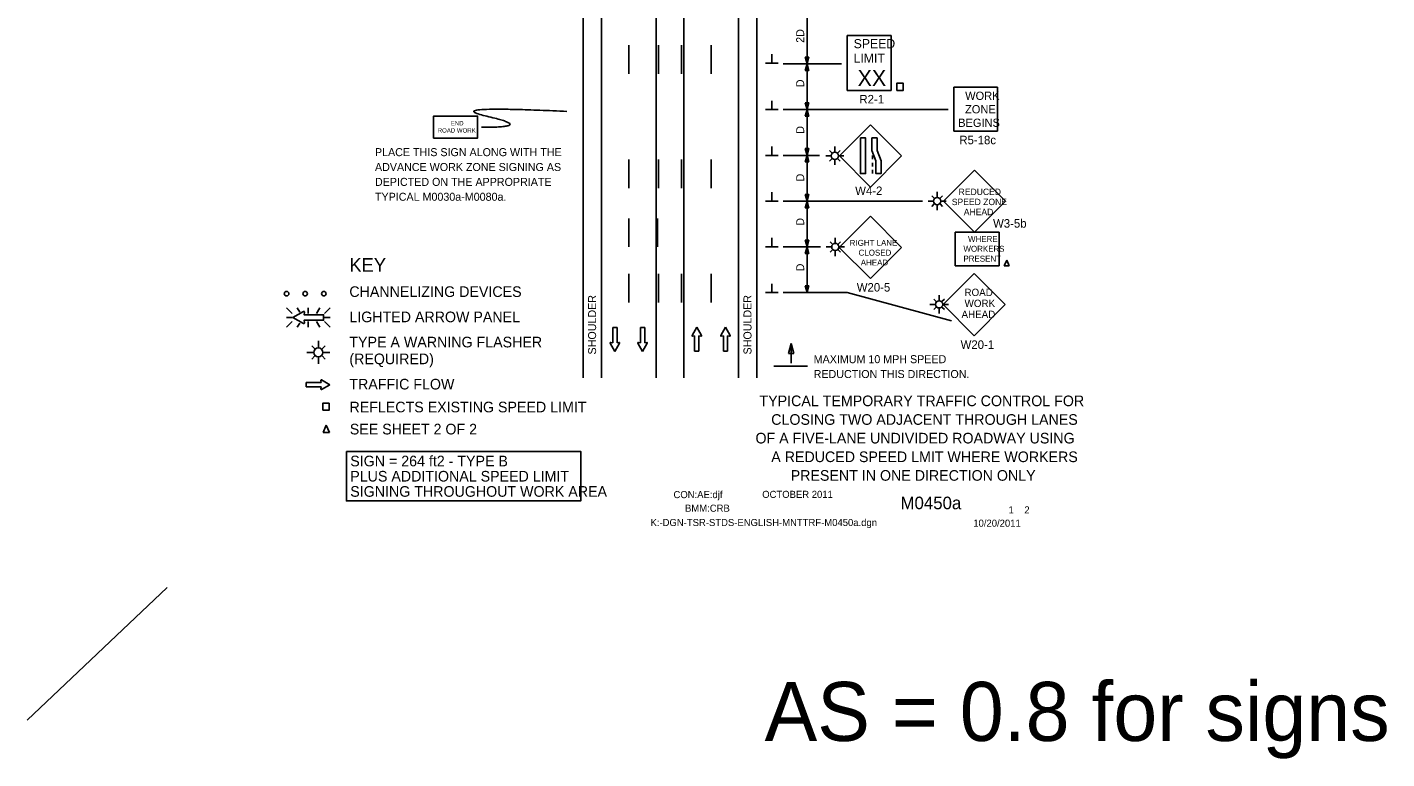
# Model space of a CAD drawing. Extents: x 16525 to 18478, y 5730 to 6925.
# Drawn here: x 16525 to 17715, y 5730 to 6370 of the extents above; entities that cross this region are included whole.
import ezdxf

# ---------------------------------------------------------------- set-up
doc = ezdxf.new("R2010")
doc.units = 0
for name, color, linetype in [('ALI_LEGAL_EX', 7, 'Continuous'), ('BORDER', 7, 'Continuous'), ('BORDER_SIGNAL_WO', 7, 'Continuous'), ('Level 3', 7, 'Continuous'), ('MT_SCRATCH_LEVEL_E', 7, 'Continuous'), ('PAVT_EDGE_EX', 7, 'Continuous'), ('TRAFFIC_SIGNS_PR', 7, 'Continuous'), ('TYPICAL_TEXT_DIMEN_EX', 7, 'Continuous'), ('TYPICAL_TEXT_DIMEN_PR', 7, 'Continuous')]:
    doc.layers.add(name, color=color, linetype=linetype)

msp = doc.modelspace()

# ---------------------------------------------------------------- linework, layer by layer
at = {"layer": 'ALI_LEGAL_EX'}
for points in [[(17051.6, 6354.2), (17051.6, 6329.2)], [(17077.6, 6354.2), (17077.6, 6329.2)], [(17097.6, 6354.2), (17097.6, 6329.2)], [(17123.6, 6354.2), (17123.6, 6329.2)], [(17051.6, 6254.2), (17051.6, 6229.2)], [(17077.6, 6254.2), (17077.6, 6229.2)], [(17097.6, 6254.2), (17097.6, 6229.2)], [(17123.6, 6254.2), (17123.6, 6229.2)], [(17051.6, 6154.2), (17051.6, 6129.2)], [(17077.6, 6154.2), (17077.6, 6129.2)], [(17097.6, 6154.2), (17097.6, 6129.2)], [(17123.6, 6154.2), (17123.6, 6129.2)]]:
    msp.add_lwpolyline(points, dxfattribs=at)
at = {"layer": 'Level 3'}
msp.add_line((17242.5, 6137.8), (17333.9, 6113), dxfattribs=at)
at = {"layer": 'MT_SCRATCH_LEVEL_E'}
for p, q in [((17041.3, 6107.2), (17037.5, 6107.2)), ((17037.5, 6107.2), (17037.5, 6093.9)), ((17041.3, 6107.2), (17037.5, 6107.2)), ((17037.5, 6107.2), (17037.5, 6093.9)), ((17041.3, 6093.9), (17041.3, 6107.2)), ((17041.3, 6093.9), (17041.3, 6107.2)), ((17065.5, 6107.2), (17061.8, 6107.2)), ((17061.8, 6107.2), (17061.8, 6093.9)), ((17065.5, 6107.2), (17061.8, 6107.2)), ((17061.8, 6107.2), (17061.8, 6093.9)), ((17065.5, 6093.9), (17065.5, 6107.2)), ((17065.5, 6093.9), (17065.5, 6107.2)), ((17111, 6107.6), (17106.9, 6100.4)), ((17111, 6107.6), (17106.9, 6100.4)), ((17115.2, 6100.4), (17111, 6107.6)), ((17115.2, 6100.4), (17111, 6107.6)), ((17136.1, 6107.6), (17132, 6100.4)), ((17136.1, 6107.6), (17132, 6100.4)), ((17140.3, 6100.4), (17136.1, 6107.6)), ((17140.3, 6100.4), (17136.1, 6107.6)), ((17035.3, 6093.5), (17039.4, 6086.3)), ((17035.3, 6093.5), (17039.4, 6086.3)), ((17037.5, 6093.9), (17035.7, 6094.2)), ((17037.5, 6093.9), (17035.7, 6094.2)), ((17039.4, 6086.3), (17043.5, 6093.5)), ((17039.4, 6086.3), (17043.5, 6093.5)), ((17043, 6094.2), (17041.3, 6093.9)), ((17043, 6094.2), (17041.3, 6093.9)), ((17059.5, 6093.5), (17063.7, 6086.3)), ((17059.5, 6093.5), (17063.7, 6086.3)), ((17061.8, 6093.9), (17060, 6094.2)), ((17061.8, 6093.9), (17060, 6094.2)), ((17063.7, 6086.3), (17067.8, 6093.5)), ((17063.7, 6086.3), (17067.8, 6093.5)), ((17067.3, 6094.2), (17065.5, 6093.9)), ((17067.3, 6094.2), (17065.5, 6093.9)), ((17107.4, 6099.7), (17109.2, 6100)), ((17107.4, 6099.7), (17109.2, 6100)), ((17109.2, 6100), (17109.2, 6086.7)), ((17109.2, 6100), (17109.2, 6086.7)), ((17112.9, 6086.7), (17112.9, 6100)), ((17112.9, 6100), (17114.7, 6099.7)), ((17112.9, 6086.7), (17112.9, 6100)), ((17112.9, 6100), (17114.7, 6099.7)), ((17132.5, 6099.7), (17134.3, 6100)), ((17132.5, 6099.7), (17134.3, 6100)), ((17134.3, 6100), (17134.3, 6086.7)), ((17134.3, 6100), (17134.3, 6086.7)), ((17138, 6086.7), (17138, 6100)), ((17138, 6100), (17139.8, 6099.7)), ((17138, 6086.7), (17138, 6100)), ((17138, 6100), (17139.8, 6099.7)), ((17109.2, 6086.7), (17112.9, 6086.7)), ((17109.2, 6086.7), (17112.9, 6086.7)), ((17134.3, 6086.7), (17138, 6086.7)), ((17134.3, 6086.7), (17138, 6086.7)), ((16782.6, 6059.1), (16769.3, 6059.1)), ((16769.3, 6059.1), (16769.3, 6055.4)), ((16782.6, 6059.1), (16769.3, 6059.1)), ((16769.3, 6059.1), (16769.3, 6055.4)), ((16769.3, 6055.4), (16782.6, 6055.4)), ((16769.3, 6055.4), (16782.6, 6055.4)), ((16782.3, 6060.9), (16782.6, 6059.1)), ((16782.3, 6060.9), (16782.6, 6059.1)), ((16782.6, 6055.4), (16782.3, 6053.6)), ((16782.6, 6055.4), (16782.3, 6053.6)), ((16790.2, 6057.3), (16782.9, 6061.4)), ((16790.2, 6057.3), (16782.9, 6061.4)), ((16782.9, 6053.1), (16790.2, 6057.3)), ((16782.9, 6053.1), (16790.2, 6057.3))]:
    msp.add_line(p, q, dxfattribs=at)
for centre, start, end in [((17107.3, 6100.1), 150.4248, 279.9638), ((17107.3, 6100.1), 150.4248, 279.9638), ((17114.8, 6100.1), 260.0362, 29.7731), ((17114.8, 6100.1), 260.0362, 29.7731), ((17132.4, 6100.1), 150.4248, 279.9638), ((17132.4, 6100.1), 150.4248, 279.9638), ((17139.9, 6100.1), 260.0362, 29.7731), ((17139.9, 6100.1), 260.0362, 29.7731), ((17035.7, 6093.8), 80.0362, 209.7731), ((17035.7, 6093.8), 80.0362, 209.7731), ((17043.1, 6093.8), 330.4248, 99.9638), ((17043.1, 6093.8), 330.4248, 99.9638), ((17059.9, 6093.8), 80.0362, 209.7731), ((17059.9, 6093.8), 80.0362, 209.7731), ((17067.4, 6093.8), 330.4248, 99.9638), ((17067.4, 6093.8), 330.4248, 99.9638), ((16782.7, 6061), 60.4248, 189.9638), ((16782.7, 6061), 60.4248, 189.9638), ((16782.7, 6053.5), 170.0362, 299.7731), ((16782.7, 6053.5), 170.0362, 299.7731)]:
    msp.add_arc(centre, 0.463, start, end, dxfattribs=at)
at = {"layer": 'PAVT_EDGE_EX'}
for p, q in [((17011.6, 6917.6), (17011.6, 6063.2)), ((17027.6, 6917.6), (17027.6, 6063.2)), ((17075.6, 6917.6), (17075.6, 6063.2)), ((17147.6, 6917.6), (17147.6, 6063.2)), ((17163.6, 6917.6), (17163.6, 6063.2)), ((17099.6, 6464.3), (17099.6, 6063.2))]:
    msp.add_line(p, q, dxfattribs=at)
for points in [[(17051.6, 6177.7), (17051.6, 6202.7)], [(17076.6, 6177.7), (17076.6, 6202.7)]]:
    msp.add_lwpolyline(points, dxfattribs=at)
at = {"layer": 'TRAFFIC_SIGNS_PR'}
for p, q in [((17242.6, 6362.6), (17281, 6362.6)), ((17242.6, 6314.6), (17242.6, 6362.6)), ((17281, 6314.6), (17281, 6362.6)), ((17242.6, 6314.6), (17281, 6314.6)), ((17335.8, 6279), (17335.8, 6317.4)), ((17335.8, 6317.4), (17374.2, 6317.4)), ((17374.2, 6279), (17374.2, 6317.4)), ((17263.1, 6284.4), (17235.9, 6257.3)), ((17290.2, 6257.3), (17263.1, 6284.4)), ((17335.8, 6279), (17374.2, 6279)), ((17228.6, 6257.4), (17223.8, 6257.4)), ((17229.3, 6259.9), (17227.2, 6262)), ((17229.3, 6254.9), (17227.2, 6252.8)), ((17231.8, 6261), (17231.8, 6265.5)), ((17234.3, 6259.9), (17236.4, 6262)), ((17234.3, 6254.9), (17236.4, 6252.8)), ((17234.9, 6257.4), (17239.8, 6257.4)), ((17235.9, 6257.3), (17263.1, 6230.1)), ((17263.1, 6230.1), (17290.2, 6257.3)), ((17264.7, 6257.8), (17264.7, 6254.6)), ((17231.8, 6249.5), (17231.8, 6253.9)), ((17264.7, 6251.4), (17264.7, 6248.2)), ((17264.7, 6245), (17264.7, 6241.8)), ((17354, 6244.9), (17326.9, 6217.8)), ((17381.2, 6217.8), (17354, 6244.9)), ((17318.8, 6220.4), (17316.7, 6222.5)), ((17321.3, 6221.4), (17321.3, 6225.9)), ((17323.8, 6220.4), (17325.9, 6222.5)), ((17318.2, 6217.8), (17313.3, 6217.8)), ((17318.8, 6215.3), (17316.7, 6213.2)), ((17321.3, 6209.9), (17321.3, 6214.3)), ((17323.8, 6215.3), (17325.9, 6213.2)), ((17324.5, 6217.8), (17329.3, 6217.8)), ((17326.9, 6217.8), (17354, 6190.6)), ((17354, 6190.6), (17381.2, 6217.8)), ((17262.9, 6204.5), (17235.7, 6177.3)), ((17290, 6177.3), (17262.9, 6204.5)), ((17232.2, 6181.2), (17232.2, 6185.7)), ((17337, 6190.5), (17375.4, 6190.5)), ((17337, 6161.1), (17337, 6190.5)), ((17375.4, 6161.1), (17375.4, 6190.5)), ((17229, 6177.7), (17224.2, 6177.7)), ((17229.7, 6180.2), (17227.6, 6182.3)), ((17229.7, 6175.2), (17227.6, 6173.1)), ((17232.2, 6169.7), (17232.2, 6174.1)), ((17234.7, 6180.2), (17236.8, 6182.3)), ((17234.7, 6175.2), (17236.8, 6173.1)), ((17235.4, 6177.7), (17240.2, 6177.7)), ((17235.7, 6177.3), (17262.9, 6150.2)), ((17262.9, 6150.2), (17290, 6177.3)), ((17337, 6161.1), (17375.4, 6161.1)), ((17353.7, 6154.4), (17326.5, 6127.3)), ((17380.9, 6127.3), (17353.7, 6154.4)), ((16752.1, 6124.6), (16757.1, 6119.6)), ((16763.9, 6120.7), (16761.7, 6124.6)), ((16771.2, 6119.6), (16771.2, 6124.6)), ((16778.5, 6119.6), (16781.3, 6124.6)), ((16785.4, 6119.6), (16790.3, 6124.6)), ((17319.9, 6127.5), (17315, 6127.5)), ((17320.5, 6130), (17318.4, 6132.1)), ((17320.5, 6125), (17318.4, 6122.9)), ((17323, 6131.1), (17323, 6135.6)), ((17325.5, 6130), (17327.7, 6132.1)), ((17325.5, 6125), (17327.7, 6122.9)), ((17326.2, 6127.5), (17331.1, 6127.5)), ((17326.5, 6127.3), (17353.7, 6100.1)), ((17353.7, 6100.1), (17380.9, 6127.3)), ((16757.1, 6116.1), (16752.1, 6116.1)), ((16752.1, 6107.6), (16757.1, 6112.5)), ((16771.2, 6112.5), (16771.2, 6107.6)), ((16781.4, 6107.6), (16778.5, 6112.5)), ((16785.4, 6116.1), (16790.3, 6116.1)), ((16785.4, 6112.5), (16790.3, 6107.6)), ((17323, 6119.5), (17323, 6124)), ((16761.7, 6107.6), (16763.8, 6111.2)), ((16777, 6088.6), (16774.4, 6091.3)), ((16780.1, 6089.9), (16780.1, 6095.6)), ((16783.3, 6088.6), (16785.9, 6091.3)), ((16776.2, 6085.5), (16770.1, 6085.5)), ((16777, 6082.4), (16774.4, 6079.7)), ((16780.1, 6075.5), (16780.1, 6081.1)), ((16783.3, 6082.4), (16785.9, 6079.7)), ((16784.1, 6085.5), (16790.2, 6085.5))]:
    msp.add_line(p, q, dxfattribs=at)
for points in [[(17286, 6314.6), (17291.6, 6314.6), (17291.6, 6320.8), (17286, 6320.8)], [(16880.9, 6272.9), (16919.3, 6272.9), (16919.3, 6292.1), (16880.9, 6292.1)], [(17254.2, 6273), (17254.2, 6241.8), (17258.7, 6241.8), (17258.7, 6273)], [(17264.3, 6273), (17264.3, 6261.9), (17267.7, 6253), (17267.7, 6241.8), (17272.2, 6241.8), (17272.2, 6253), (17268.8, 6261.9), (17268.8, 6273)], [(16783.9, 6034.9), (16789.5, 6034.9), (16789.5, 6041.1), (16783.9, 6041.1)]]:
    msp.add_lwpolyline(points, close=True, dxfattribs=at)
for points in [[(17382.1, 6166.1), (17379.9, 6161.1)], [(17379.9, 6161.1), (17382.1, 6166.1)], [(17379.9, 6161.1), (17384.3, 6161.1)], [(17384.3, 6161.1), (17379.9, 6161.1)], [(17384.3, 6161.1), (17382.1, 6166.1)], [(17382.1, 6166.1), (17384.3, 6161.1)], [(16767.2, 6121.3), (16757.9, 6116.1), (16767.2, 6110.7)], [(16768, 6111.4), (16767.6, 6113.6), (16784.6, 6113.6), (16784.6, 6118.4), (16767.6, 6118.4), (16768, 6120.7)], [(16787, 6021.8), (16784.2, 6015.6)], [(16784.2, 6015.6), (16787, 6021.8)], [(16789.8, 6015.6), (16787, 6021.8)], [(16787, 6021.8), (16789.8, 6015.6)], [(16784.2, 6015.6), (16789.8, 6015.6)], [(16789.8, 6015.6), (16784.2, 6015.6)]]:
    msp.add_lwpolyline(points, dxfattribs=at)
for centre, radius in [((17231.8, 6257.4), 3.15), ((17321.3, 6217.8), 3.15), ((17232.2, 6177.7), 3.15), ((16752.3, 6136.9), 2), ((16768.6, 6136.9), 2), ((16784.9, 6136.9), 2), ((17323, 6127.5), 3.15), ((16780.1, 6085.5), 3.94)]:
    msp.add_circle(centre, radius, dxfattribs=at)
for centre, radius, start, end in [((16767.4, 6120.8), 0.598, 350.7308, 118.8916), ((16767.4, 6111.3), 0.597, 241.4833, 9.9593)]:
    msp.add_arc(centre, radius, start, end, dxfattribs=at)
msp.add_open_spline([(16922.9, 6282.3), (16970.1, 6282.3), (16885.1, 6301.6), (16997.4, 6296.2)], degree=2, dxfattribs=at)
at = {"layer": 'TYPICAL_TEXT_DIMEN_EX'}
msp.add_lwpolyline([(16804.7, 5999), (17009.6, 5999), (17009.6, 5955.6), (16804.7, 5955.6)], close=True, dxfattribs=at)
at = {"layer": 'TYPICAL_TEXT_DIMEN_PR'}
for p, q in [((17207.6, 6377.8), (17207.6, 6337.8)), ((17182.3, 6338.5), (17171.1, 6338.5)), ((17176.7, 6338.5), (17176.7, 6346.3)), ((17207.6, 6337.8), (17206, 6343.7)), ((17206, 6343.7), (17207.6, 6343.7)), ((17207.6, 6343.7), (17209.2, 6343.7)), ((17209.2, 6343.7), (17207.6, 6337.8)), ((17186.6, 6337.8), (17237.6, 6337.8)), ((17206, 6332), (17207.6, 6337.8)), ((17207.6, 6332), (17206, 6332)), ((17207.6, 6337.8), (17207.6, 6297.8)), ((17207.6, 6337.8), (17209.2, 6332)), ((17209.2, 6332), (17207.6, 6332)), ((17176.7, 6297.8), (17176.7, 6305.6)), ((17207.6, 6297.8), (17206, 6303.7)), ((17206, 6303.7), (17207.6, 6303.7)), ((17207.6, 6303.7), (17209.2, 6303.7)), ((17209.2, 6303.7), (17207.6, 6297.8)), ((17182.3, 6297.8), (17171.1, 6297.8)), ((17186.6, 6297.8), (17330.8, 6297.8)), ((17206, 6292), (17207.6, 6297.8)), ((17207.6, 6292), (17206, 6292)), ((17207.6, 6297.8), (17207.6, 6257.8)), ((17207.6, 6297.8), (17209.2, 6292)), ((17209.2, 6292), (17207.6, 6292)), ((17182.3, 6257.8), (17171.1, 6257.8)), ((17176.7, 6257.8), (17176.7, 6265.6)), ((17186.6, 6257.8), (17218.4, 6257.8)), ((17207.6, 6257.8), (17206, 6263.7)), ((17206, 6263.7), (17207.6, 6263.7)), ((17206, 6252), (17207.6, 6257.8)), ((17207.6, 6263.7), (17209.2, 6263.7)), ((17209.2, 6263.7), (17207.6, 6257.8)), ((17207.6, 6257.8), (17207.6, 6217.8)), ((17207.6, 6257.8), (17209.2, 6252)), ((17207.6, 6252), (17206, 6252)), ((17209.2, 6252), (17207.6, 6252)), ((17176.7, 6217.8), (17176.7, 6225.6)), ((17207.6, 6217.8), (17206, 6223.7)), ((17206, 6223.7), (17207.6, 6223.7)), ((17207.6, 6223.7), (17209.2, 6223.7)), ((17209.2, 6223.7), (17207.6, 6217.8)), ((17182.3, 6217.8), (17171.1, 6217.8)), ((17186.6, 6217.8), (17308.6, 6217.8)), ((17206, 6212), (17207.6, 6217.8)), ((17207.6, 6212), (17206, 6212)), ((17207.6, 6217.8), (17207.6, 6177.8)), ((17207.6, 6217.8), (17209.2, 6212)), ((17209.2, 6212), (17207.6, 6212)), ((17176.7, 6177.8), (17176.7, 6185.6)), ((17207.6, 6177.8), (17206, 6183.7)), ((17206, 6183.7), (17207.6, 6183.7)), ((17207.6, 6183.7), (17209.2, 6183.7)), ((17209.2, 6183.7), (17207.6, 6177.8)), ((17182.3, 6177.8), (17171.1, 6177.8)), ((17186.6, 6177.8), (17219.3, 6177.8)), ((17206, 6172), (17207.6, 6177.8)), ((17207.6, 6172), (17206, 6172)), ((17207.6, 6177.8), (17207.6, 6137.8)), ((17207.6, 6177.8), (17209.2, 6172)), ((17209.2, 6172), (17207.6, 6172)), ((17182.3, 6137.8), (17171.1, 6137.8)), ((17176.7, 6137.8), (17176.7, 6145.6)), ((17186.6, 6137.8), (17242.5, 6137.8)), ((17207.6, 6137.8), (17206, 6143.7)), ((17206, 6143.7), (17207.6, 6143.7)), ((17207.6, 6143.7), (17209.2, 6143.7)), ((17209.2, 6143.7), (17207.6, 6137.8)), ((17191.3, 6084.5), (17193.6, 6093.3)), ((17193.6, 6076.1), (17193.6, 6093.3)), ((17193.6, 6093.3), (17196, 6084.5)), ((17193.6, 6084.5), (17191.3, 6084.5)), ((17196, 6084.5), (17193.6, 6084.5)), ((17207.8, 6073.6), (17178.4, 6073.6)), ((16647.8, 5880), (16525.4, 5763.9))]:
    msp.add_line(p, q, dxfattribs=at)

# ---------------------------------------------------------------- texts
at = {"layer": 'BORDER'}
for s, p in [('TYPICAL TEMPORARY TRAFFIC CONTROL FOR', (17165.9, 6038.5)), ('CLOSING TWO ADJACENT THROUGH LANES', (17176.2, 6022.2)), ('OF A FIVE-LANE UNDIVIDED ROADWAY USING', (17162.4, 6005.9)), ('A REDUCED SPEED LMIT WHERE WORKERS', (17176.2, 5989.6)), ('PRESENT IN ONE DIRECTION ONLY', (17193.2, 5973.3))]:
    msp.add_text(s, height=9.3, dxfattribs=at).set_placement(p)
at = {"layer": 'BORDER_SIGNAL_WO'}
for s, height, p in [('CON:AE:djf', 6.2, (17090.7, 5958.1)), ('    OCTOBER 2011    ', 6.2, (17159.1, 5958.3)), ('    M0450a   ', 11, (17272.9, 5948.4)), ('BMM:CRB   ', 6.2, (17100.8, 5946.2)), (' 1    2 ', 6.2, (17381.4, 5944.7)), ('K:-DGN-TSR-STDS-ENGLISH-MNTTRF-M0450a.dgn         ', 6.2, (17070.6, 5933.7)), ('10/20/2011    ', 6.2, (17352.9, 5933.1)), ('AS = 0.8 for signs', 51.61, (17170.4, 5745.8))]:
    msp.add_text(s, height=height, dxfattribs=at).set_placement(p)
at = {"layer": 'TRAFFIC_SIGNS_PR'}
for s, height, p in [('SPEED', 8, (17248.3, 6351.5)), ('LIMIT', 8, (17248.2, 6338.7)), ('XX', 14.03, (17251.7, 6318.4)), ('R2-1', 7.44, (17253.3, 6303.2)), ('WORK', 7.22, (17345.8, 6306.3)), ('ZONE', 7.22, (17345.7, 6294.5)), ('ROAD WORK', 3.83, (16884.5, 6277.7)), ('END', 3.83, (16895.9, 6284)), ('BEGINS', 7.22, (17339.7, 6282.7)), ('R5-18c', 7.44, (17340.7, 6267.5)), ('PLACE THIS SIGN ALONG WITH THE', 7, (16829.6, 6257.1)), ('ADVANCE WORK ZONE SIGNING AS', 7, (16829.6, 6244.1)), ('DEPICTED ON THE APPROPRIATE', 7, (16829.6, 6231.1)), ('TYPICAL M0030a-M0080a.', 7, (16829.6, 6218.1)), ('W4-2', 7.44, (17249.6, 6223.1)), ('SPEED ZONE', 5.6, (17334.1, 6214.3)), ('REDUCED', 5.6, (17340.1, 6223.1)), ('AHEAD', 5.6, (17344.6, 6205.5)), ('W3-5b', 7.44, (17370.2, 6194.6)), ('RIGHT LANE', 5.2, (17244.8, 6178.7)), ('WHERE', 5.2, (17348.3, 6182.1)), ('CLOSED', 5.2, (17252.6, 6170.1)), ('WORKERS', 5.2, (17344.3, 6173.5)), ('AHEAD', 5.2, (17254.5, 6161.5)), ('PRESENT', 5.2, (17344.3, 6164.9)), ('W20-5', 7.44, (17251, 6138.7)), ('ROAD', 6.41, (17345.2, 6134.8)), ('WORK', 6.41, (17345.3, 6125.2)), ('AHEAD', 6.41, (17342.6, 6115.6)), ('W20-1', 7.45, (17341.8, 6088.6))]:
    msp.add_text(s, height=height, dxfattribs=at).set_placement(p)
at = {"layer": 'TYPICAL_TEXT_DIMEN_EX'}
for s, height, p in [('KEY', 12, (16807.2, 6156)), ('CHANNELIZING DEVICES', 9.3, (16807.2, 6134)), ('LIGHTED ARROW PANEL', 9.3, (16807.2, 6111.9)), ('TYPE A WARNING FLASHER', 9.3, (16807.2, 6089.9)), ('(REQUIRED)', 9.3, (16807.2, 6075.2)), ('TRAFFIC FLOW', 9.3, (16807.2, 6053.1)), ('REFLECTS EXISTING SPEED LIMIT', 9.3, (16807.3, 6033.1)), ('SEE SHEET 2 OF 2', 9.3, (16807.6, 6013.8)), ('SIGN = 264 ft2 - TYPE B', 9.3, (16808, 5985.9)), ('PLUS ADDITIONAL SPEED LIMIT', 9.3, (16808, 5972.6)), ('SIGNING THROUGHOUT WORK AREA', 9.3, (16808, 5959.3))]:
    msp.add_text(s, height=height, dxfattribs=at).set_placement(p)
at = {"layer": 'TYPICAL_TEXT_DIMEN_PR'}
for s, p in [('2D', (17205, 6356.2)), ('D', (17205, 6317.4)), ('D', (17205, 6276.7)), ('D', (17205, 6235)), ('D', (17205, 6196.3)), ('D', (17205, 6156.4)), ('SHOULDER', (17023, 6083.7)), ('SHOULDER', (17158.9, 6083.7))]:
    msp.add_text(s, height=7, rotation=90, dxfattribs=at).set_placement(p)
for s, p in [('MAXIMUM 10 MPH SPEED', (17213.3, 6076.1)), ('REDUCTION THIS DIRECTION.', (17213.3, 6063.1))]:
    msp.add_text(s, height=7, dxfattribs=at).set_placement(p)

doc.saveas('drawing.dxf')
